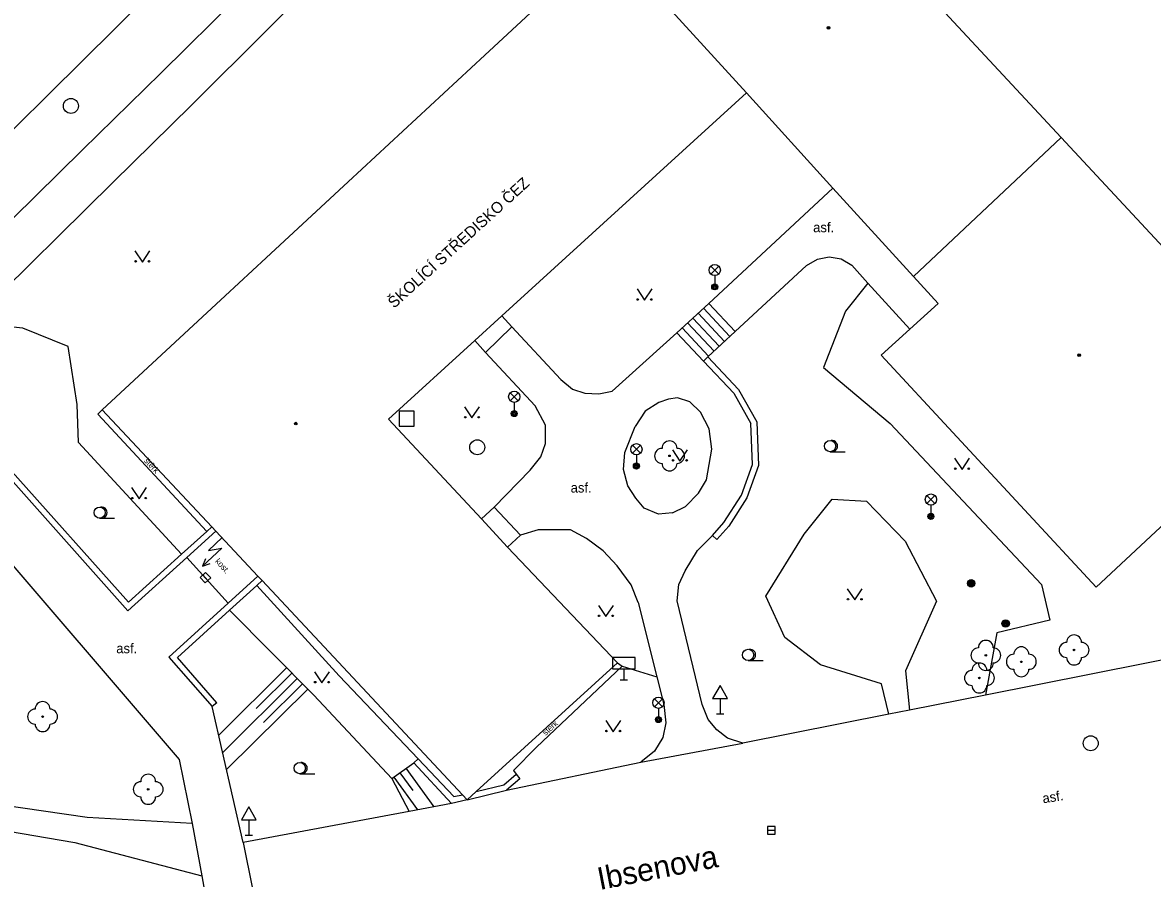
# Model space of a CAD drawing. Extents: x -598233 to -596890, y -1157848 to -1156431.
# Drawn here: x -597043.4 to -596967.9, y -1157042.3 to -1156985.2 of the extents above; entities that cross this region are included whole.
import ezdxf

# ---------------------------------------------------------------- set-up
doc = ezdxf.new("R2010")
doc.units = 0
for name, color, linetype in [('Level 10', 7, 'Continuous'), ('Level 11', 7, 'Continuous'), ('Level 14', 7, 'Continuous'), ('Level 15', 7, 'Continuous'), ('Level 21', 7, 'Continuous'), ('Level 22', 7, 'Continuous'), ('Level 23', 7, 'Continuous'), ('Level 25', 7, 'Continuous'), ('Level 26', 7, 'Continuous'), ('Level 27', 7, 'Continuous'), ('Level 33', 7, 'Continuous'), ('Level 34', 7, 'Continuous'), ('Level 36', 7, 'Continuous'), ('Level 39', 7, 'Continuous'), ('Level 40', 7, 'Continuous'), ('Level 41', 7, 'Continuous'), ('Level 49', 7, 'Continuous'), ('Level 5', 7, 'Continuous'), ('Level 7', 7, 'Continuous')]:
    doc.layers.add(name, color=color, linetype=linetype)

msp = doc.modelspace()

# ---------------------------------------------------------------- linework, layer by layer
at = {"layer": 'Level 10'}
for points in [[(-597093.49, -1157040.95), (-597092.66, -1157040.13), (-597070.05, -1157017.68), (-597057.21, -1157005.4), (-597028.29, -1156976.75), (-597022.59, -1156970.93), (-597012.03, -1156959.64)], [(-596954.24, -1157025.17), (-596979.09, -1157030.11), (-596984.17, -1157031.12), (-596985.55, -1157031.39), (-596995.29, -1157033.32)], [(-597002.11, -1157034.6), (-596995.29, -1157033.32)], [(-597011.08, -1157036.4699), (-597002.11, -1157034.6)], [(-597014.74, -1157037.35), (-597017.58, -1157037.88), (-597028.65, -1157039.95)], [(-597028.65, -1157039.95), (-597027.43, -1157046.02), (-597030.62, -1157046.71)]]:
    msp.add_lwpolyline(points, dxfattribs=at)
at = {"layer": 'Level 11'}
for points in [[(-597023.83, -1156978.25), (-597028.97, -1156983.44), (-597034.16, -1156988.6), (-597039.38, -1156993.71)], [(-597021.83, -1156980.42), (-597026.96, -1156985.61), (-597032.13, -1156990.76), (-597037.33, -1156995.87)], [(-597039.38, -1156993.71), (-597053.39, -1157007.48)], [(-597046.85, -1157005.25), (-597046.5, -1157004.91), (-597037.33, -1156995.87)], [(-596997.56, -1157003.96), (-596989.28, -1156996.26)], [(-596991.04, -1157001.43), (-596990.32, -1157001), (-596989.53, -1157000.86), (-596988.73, -1157000.98), (-596988.02, -1157001.4099)], [(-596991.04, -1157001.43), (-596995.81, -1157005.83)], [(-596988.02, -1157001.4099), (-596986.94, -1157002.6), (-596984.15, -1157005.68)], [(-596999.7, -1157005.93), (-596997.56, -1157003.96)], [(-596997.56, -1157003.96), (-596995.81, -1157005.83)], [(-597011.39, -1157004.79), (-597010.7199, -1157005.52)], [(-596998.27, -1157004.61), (-596996.51, -1157006.5)], [(-596997.92, -1157004.28), (-596996.1599, -1157006.17)], [(-597039.74, -1157010.72), (-597040.34, -1157006.85), (-597043.38, -1157005.62), (-597046.85, -1157005.25)], [(-597012.48, -1157007.24), (-597010.7199, -1157005.52)], [(-597010.7199, -1157005.52), (-597007.45, -1157009.04)], [(-596998.98, -1157005.27), (-596997.2199, -1157007.15)], [(-596998.63, -1157004.94), (-596996.87, -1157006.82)], [(-597004.01, -1157009.82), (-596999.7, -1157005.93)], [(-596999.7, -1157005.93), (-596997.93, -1157007.81)], [(-596999.34, -1157005.6), (-596997.58, -1157007.48)], [(-596995.81, -1157005.83), (-596997.64, -1157007.53)], [(-597013.2, -1157006.44), (-597012.48, -1157007.24)], [(-597009.17, -1157010.8), (-597012.48, -1157007.24)], [(-597050.8, -1157009.08), (-597048.61, -1157010.92), (-597046.34, -1157018.82), (-597032.93, -1157034.4099), (-597032.07, -1157038.68)], [(-597007.45, -1157009.04), (-597006.67, -1157009.69), (-597005.85, -1157009.95), (-597004.92, -1157010.01), (-597004.01, -1157009.82)], [(-597009.49, -1157015.1), (-597008.78, -1157014.2), (-597008.48, -1157013.32), (-597008.48, -1157012.09), (-597009.17, -1157010.8)], [(-597000, -1157017.95), (-596999.12, -1157017.53), (-596998.25, -1157016.62), (-596997.72, -1157015.75), (-596997.36, -1157013.7), (-596997.55, -1157012.34), (-596998.12, -1157011.22), (-596998.84, -1157010.53), (-596999.66, -1157010.27), (-597000.26, -1157010.36), (-597000.9099, -1157010.57), (-597001.81, -1157011.1599), (-597002.48, -1157012.18)], [(-597038.07, -1157011.07), (-597038.36, -1157011.35)], [(-597031.09, -1157019.18), (-597038.36, -1157011.35)], [(-597003.18, -1157013.92), (-597002.48, -1157012.18)], [(-597000, -1157017.95), (-597000.92, -1157018.03), (-597001.89, -1157017.63), (-597002.44, -1157016.96), (-597002.98, -1157016.15), (-597003.27, -1157015.05), (-597003.18, -1157013.92)], [(-597044.25, -1157015.01), (-597036.32, -1157023.91)], [(-597011.9, -1157017.56), (-597009.49, -1157015.1)], [(-597011.9, -1157017.56), (-597012.75, -1157018.35)], [(-597011.9, -1157017.56), (-597010.14, -1157019.44)], [(-597032.77, -1157020.7), (-597031.09, -1157019.18), (-597030.76, -1157018.88)], [(-597002.28, -1157023.94), (-597002.76, -1157022.75), (-597003.68, -1157021.49), (-597004.62, -1157020.47), (-597005.73, -1157019.65), (-597006.81, -1157019.09), (-597008.95, -1157019.07), (-597010.14, -1157019.44)], [(-597010.14, -1157019.44), (-597011, -1157020.24)], [(-596999.67, -1157023.83), (-596999.57, -1157022.73), (-596999.14, -1157021.82), (-596998.32, -1157020.45), (-596997.33, -1157019.46)], [(-597036.32, -1157023.91), (-597032.77, -1157020.7)], [(-597029.66, -1157023.98), (-597032.42, -1157020.93)], [(-597030.42, -1157030.62), (-597033.05, -1157027.6), (-597029.58, -1157024.45), (-597027.75, -1157022.79), (-597027.4, -1157022.47)], [(-597016.98, -1157034.36), (-597022.25, -1157028.82), (-597027.75, -1157022.79)], [(-597002.28, -1157023.94), (-597001.03, -1157028.89), (-597000.57, -1157030.73)], [(-596998.02, -1157030.75), (-596999.67, -1157023.83)], [(-597003.66, -1157027.96), (-597003.35, -1157028.19), (-597009.07, -1157033.58), (-597010.61, -1157035.15), (-597010.44, -1157035.4)], [(-597032.07, -1157038.68), (-597039.07, -1157038.29), (-597049.37, -1157036.79), (-597050.83, -1157036.44), (-597056.04, -1157035.05), (-597064.62, -1157032.14), (-597067.53, -1157031.15), (-597071.87, -1157029.68)], [(-597028.65, -1157039.95), (-597030.72, -1157030.88)], [(-597000.57, -1157030.73), (-597000.43, -1157031.9699), (-597000.64, -1157032.94), (-597001.19, -1157033.85), (-597002.11, -1157034.6)], [(-596995.29, -1157033.32), (-596996.33, -1157032.98), (-596997.03, -1157032.44), (-596997.62, -1157031.74), (-596998.02, -1157030.75)], [(-597074.68, -1157032.39), (-597072.64, -1157032.29), (-597067.89, -1157032.73), (-597065.43, -1157033.55), (-597056.76, -1157036.46), (-597049.69, -1157038.28), (-597039.89, -1157039.95), (-597031.4099, -1157042.18)], [(-597016.98, -1157034.36), (-597014.59, -1157036.89), (-597014.01, -1157036.76)], [(-597032.07, -1157038.68), (-597031.4099, -1157042.18)], [(-597031.4099, -1157042.18), (-597030.62, -1157046.71)]]:
    msp.add_lwpolyline(points, dxfattribs=at)
at = {"layer": 'Level 14'}
msp.add_lwpolyline([(-597018.73, -1157035.69), (-597017.27, -1157034.63)], dxfattribs=at)
at = {"layer": 'Level 15'}
for points in [[(-597025.76, -1157028.3), (-597030.28, -1157032.79)], [(-597025.41, -1157028.65), (-597027.78, -1157031.01)], [(-597025.05, -1157029.01), (-597030.02, -1157033.94)], [(-597024.7, -1157029.36), (-597027.3, -1157031.94)], [(-597024.35, -1157029.72), (-597029.76, -1157035.09)], [(-597018.6, -1157035.59), (-597017.01, -1157037.77)], [(-597018.19, -1157035.3), (-597017.33, -1157036.49)], [(-597017.79, -1157035), (-597015.92, -1157037.57)]]:
    msp.add_lwpolyline(points, dxfattribs=at)
at = {"layer": 'Level 21'}
for points in [[(-596986.94, -1157002.6), (-596988.44, -1157004.48), (-596989.9, -1157008.24), (-596985.46, -1157011.99), (-596975.36, -1157022.73), (-596974.8, -1157025.1), (-596978.34, -1157025.96), (-596979.09, -1157030.11)], [(-597032.77, -1157020.7), (-597039.65, -1157013.25), (-597039.74, -1157010.72)], [(-596985.55, -1157031.39), (-596986.03, -1157029.35), (-596990.12, -1157028.1), (-596992.5, -1157026.27), (-596993.76, -1157023.5), (-596991.2, -1157019.37), (-596989.34, -1157017.04), (-596987.04, -1157017.17), (-596984.46, -1157019.83), (-596982.37, -1157023.85), (-596984.43, -1157028.5), (-596984.17, -1157031.12)], [(-597029.58, -1157024.45), (-597023.95, -1157030.12), (-597018.73, -1157035.69), (-597017.58, -1157037.88)]]:
    msp.add_lwpolyline(points, dxfattribs=at)
at = {"layer": 'Level 22'}
for centre in [(-597000.19, -1157014.14), (-596979.07, -1157027.46), (-596973.18, -1157027.1), (-596976.7, -1157027.89), (-596979.5, -1157028.97), (-597042.05, -1157031.55), (-597035, -1157036.4)]:
    msp.add_circle(centre, 0.05, dxfattribs=at)
for centre, start, end in [((-597000.69, -1157014.14), 90, 270), ((-597000.19, -1157013.64), 0, 180), ((-596999.69, -1157014.14), 270, 90), ((-597000.19, -1157014.64), 180, 0), ((-596979.07, -1157026.96), 0, 180), ((-596973.68, -1157027.1), 90, 270), ((-596973.18, -1157026.6), 0, 180), ((-596972.68, -1157027.1), 270, 90), ((-596979.57, -1157027.46), 90, 270), ((-596978.57, -1157027.46), 270, 90), ((-596977.2, -1157027.89), 90, 270), ((-596976.7, -1157027.39), 0, 180), ((-596976.2, -1157027.89), 270, 90), ((-596979.5, -1157028.47), 0, 180), ((-596979.07, -1157027.96), 180, 0), ((-596973.18, -1157027.6), 180, 0), ((-596980, -1157028.97), 90, 270), ((-596979, -1157028.97), 270, 90), ((-596976.7, -1157028.39), 180, 0), ((-596979.5, -1157029.47), 180, 0), ((-597042.55, -1157031.55), 90, 270), ((-597042.05, -1157031.05), 0, 180), ((-597041.55, -1157031.55), 270, 90), ((-597042.05, -1157032.05), 180, 0), ((-597035, -1157035.9), 0, 180), ((-597035.5, -1157036.4), 90, 270), ((-597034.5, -1157036.4), 270, 90), ((-597035, -1157036.9), 180, 0)]:
    msp.add_arc(centre, 0.5, start, end, dxfattribs=at)
at = {"layer": 'Level 23'}
msp.add_lwpolyline([(-597003.35, -1157028.19), (-597001.03, -1157028.89)], dxfattribs=at)
at = {"layer": 'Level 25'}
for centre, radius in [((-596980.05, -1157022.65), 0.25), ((-596980.05, -1157022.65), 0.2), ((-596980.05, -1157022.65), 0.15), ((-596980.05, -1157022.65), 0.1), ((-596980.05, -1157022.65), 0.05), ((-596977.75, -1157025.33), 0.25), ((-596977.75, -1157025.33), 0.2), ((-596977.75, -1157025.33), 0.15), ((-596977.75, -1157025.33), 0.1), ((-596977.75, -1157025.33), 0.05)]:
    msp.add_circle(centre, radius, dxfattribs=at)
at = {"layer": 'Level 26'}
msp.add_lwpolyline([(-597018.24, -1157012.15), (-597017.24, -1157012.15), (-597017.24, -1157011.15), (-597018.24, -1157011.15)], close=True, dxfattribs=at)
at = {"layer": 'Level 27'}
for p, q in [((-597031.0123, -1157022.4554), (-597031.3477, -1157022.0846)), ((-596993.64, -1157039.14), (-596993.14, -1157039.14))]:
    msp.add_line(p, q, dxfattribs=at)
for points in [[(-597030.8269, -1157022.2876), (-597031.1624, -1157021.9169), (-597031.5331, -1157022.2524), (-597031.1976, -1157022.6231)], [(-596993.64, -1157039.39), (-596993.14, -1157039.39), (-596993.14, -1157038.89), (-596993.64, -1157038.89)]]:
    msp.add_lwpolyline(points, close=True, dxfattribs=at)
for centre in [(-597040.1599, -1156990.78), (-597013.03, -1157013.57), (-596972.07, -1157033.33)]:
    msp.add_circle(centre, 0.5, dxfattribs=at)
at = {"layer": 'Level 33'}
for p, q in [((-596997.435, -1157002), (-596996.905, -1157001.47)), ((-596997.435, -1157001.47), (-596996.905, -1157002)), ((-596997.17, -1157002.11), (-596997.17, -1157002.86)), ((-597010.825, -1157010.46), (-597010.295, -1157009.93)), ((-597010.825, -1157009.93), (-597010.295, -1157010.46)), ((-597010.56, -1157010.57), (-597010.56, -1157011.32)), ((-597002.665, -1157013.96), (-597002.135, -1157013.43)), ((-597002.665, -1157013.43), (-597002.135, -1157013.96)), ((-597002.4, -1157014.07), (-597002.4, -1157014.82)), ((-596983.005, -1157017.32), (-596982.475, -1157016.79)), ((-596983.005, -1157016.79), (-596982.475, -1157017.32)), ((-596982.74, -1157017.43), (-596982.74, -1157018.18)), ((-597001.195, -1157030.89), (-597000.665, -1157030.36)), ((-597001.195, -1157030.36), (-597000.665, -1157030.89)), ((-597000.93, -1157031), (-597000.93, -1157031.75))]:
    msp.add_line(p, q, dxfattribs=at)
for centre, radius in [((-596997.17, -1157001.735), 0.375), ((-596997.17, -1157002.86), 0.2), ((-596997.17, -1157002.86), 0.1445), ((-596997.17, -1157002.86), 0.0876), ((-597010.56, -1157010.195), 0.375), ((-597010.56, -1157011.32), 0.2), ((-597010.56, -1157011.32), 0.1445), ((-597010.56, -1157011.32), 0.0876), ((-597002.4, -1157013.695), 0.375), ((-597002.4, -1157014.82), 0.2), ((-597002.4, -1157014.82), 0.1445), ((-597002.4, -1157014.82), 0.0876), ((-596982.74, -1157017.055), 0.375), ((-596982.74, -1157018.18), 0.2), ((-596982.74, -1157018.18), 0.1445), ((-596982.74, -1157018.18), 0.0876), ((-597000.93, -1157030.625), 0.375), ((-597000.93, -1157031.75), 0.2), ((-597000.93, -1157031.75), 0.1445), ((-597000.93, -1157031.75), 0.0876)]:
    msp.add_circle(centre, radius, dxfattribs=at)
at = {"layer": 'Level 34'}
for p, q in [((-597003.24, -1157028.35), (-597003.24, -1157029.1)), ((-597003.49, -1157029.1), (-597002.99, -1157029.1)), ((-596996.81, -1157030.342), (-596996.81, -1157031.36)), ((-596997.06, -1157031.36), (-596996.56, -1157031.36)), ((-597028.28, -1157038.442), (-597028.28, -1157039.46)), ((-597028.53, -1157039.46), (-597028.03, -1157039.46))]:
    msp.add_line(p, q, dxfattribs=at)
for points in [[(-597003.99, -1157028.35), (-597002.49, -1157028.35), (-597002.49, -1157027.6), (-597003.99, -1157027.6)], [(-596997.31, -1157030.342), (-596996.31, -1157030.342), (-596996.81, -1157029.476)], [(-597028.78, -1157038.442), (-597027.78, -1157038.442), (-597028.28, -1157037.576)]]:
    msp.add_lwpolyline(points, close=True, dxfattribs=at)
at = {"layer": 'Level 36'}
for p, q in [((-596989.47, -1157013.865), (-596988.47, -1157013.865)), ((-597038.24, -1157018.305), (-597037.24, -1157018.305)), ((-596994.94, -1157027.805), (-596993.94, -1157027.805)), ((-597024.88, -1157035.365), (-597023.88, -1157035.365))]:
    msp.add_line(p, q, dxfattribs=at)
for points in [[(-597035.89, -1157000.45), (-597035.39, -1157001.2), (-597034.89, -1157000.45)], [(-597002.36, -1157003), (-597001.86, -1157003.75), (-597001.36, -1157003)], [(-597013.88, -1157010.86), (-597013.38, -1157011.61), (-597012.88, -1157010.86)], [(-597000, -1157013.74), (-596999.5, -1157014.49), (-596999, -1157013.74)], [(-596981.16, -1157014.3), (-596980.66, -1157015.05), (-596980.16, -1157014.3)], [(-597036.11, -1157016.26), (-597035.61, -1157017.01), (-597035.11, -1157016.26)], [(-597030.07, -1157019.6), (-597030.9823, -1157020.4546), (-597030.0931, -1157020.3067), (-597031.3702, -1157021.5031)], [(-597031.1631, -1157021.009), (-597031.3702, -1157021.5031), (-597030.8636, -1157021.3286)], [(-596988.32, -1157023.01), (-596987.82, -1157023.76), (-596987.32, -1157023.01)], [(-597004.94, -1157024.12), (-597004.44, -1157024.87), (-597003.94, -1157024.12)], [(-597023.9, -1157028.55), (-597023.4, -1157029.3), (-597022.9, -1157028.55)], [(-597004.45, -1157031.81), (-597003.95, -1157032.56), (-597003.45, -1157031.81)]]:
    msp.add_lwpolyline(points, dxfattribs=at)
for centre, radius in [((-597035.8402, -1157001.1498), 0.05), ((-597034.9408, -1157001.1498), 0.05), ((-597002.3102, -1157003.6998), 0.05), ((-597001.4108, -1157003.6998), 0.05), ((-597013.8302, -1157011.5598), 0.05), ((-597012.9308, -1157011.5598), 0.05), ((-596989.47, -1157013.4896), 0.375), ((-596999.9502, -1157014.4398), 0.05), ((-596999.0508, -1157014.4398), 0.05), ((-596981.1102, -1157014.9998), 0.05), ((-596980.2108, -1157014.9998), 0.05), ((-597038.24, -1157017.9296), 0.375), ((-597036.0602, -1157016.9598), 0.05), ((-597035.1608, -1157016.9598), 0.05), ((-596988.2702, -1157023.7098), 0.05), ((-596987.3708, -1157023.7098), 0.05), ((-597004.8902, -1157024.8198), 0.05), ((-597003.9908, -1157024.8198), 0.05), ((-596994.94, -1157027.4296), 0.375), ((-597023.8502, -1157029.2498), 0.05), ((-597022.9508, -1157029.2498), 0.05), ((-597004.4002, -1157032.5098), 0.05), ((-597003.5008, -1157032.5098), 0.05), ((-597024.88, -1157034.9896), 0.375)]:
    msp.add_circle(centre, radius, dxfattribs=at)
for centre in [(-596989.345, -1157013.4896), (-597038.115, -1157017.9296), (-596994.815, -1157027.4296), (-597024.755, -1157034.9896)]:
    msp.add_arc(centre, 0.375, 260.405931, 99.594069, dxfattribs=at)
at = {"layer": 'Level 39'}
for centre, radius in [((-596989.57, -1156985.56), 0.09), ((-596989.57, -1156985.56), 0.0398), ((-596972.84, -1157007.42), 0.09), ((-596972.84, -1157007.42), 0.0398), ((-597025.15, -1157011.99), 0.09), ((-597025.15, -1157011.99), 0.0398)]:
    msp.add_circle(centre, radius, dxfattribs=at)
at = {"layer": 'Level 5'}
for points in [[(-596995.56, -1156969.74), (-596974.03, -1156992.89)], [(-597004.31, -1156979.76), (-597038.07, -1157011.07)], [(-597004.31, -1156979.76), (-596995.06, -1156989.9099)], [(-596995.06, -1156989.9099), (-597011.39, -1157004.79)], [(-596995.06, -1156989.9099), (-596989.28, -1156996.26)], [(-596974.03, -1156992.89), (-596983.9, -1157002.17)], [(-596974.03, -1156992.89), (-596958, -1157010.14)], [(-596989.28, -1156996.26), (-596983.9, -1157002.17)], [(-596983.9, -1157002.17), (-596982.26, -1157003.96)], [(-596982.26, -1157003.96), (-596984.15, -1157005.68)], [(-597011.39, -1157004.79), (-597013.2, -1157006.44)], [(-596984.15, -1157005.68), (-596986.05, -1157007.4099)], [(-597013.2, -1157006.44), (-597018.95, -1157011.68)], [(-596986.05, -1157007.4099), (-596971.71, -1157022.9)], [(-597030.76, -1157018.88), (-597038.07, -1157011.07)], [(-597018.95, -1157011.68), (-597012.75, -1157018.35)], [(-596965.75, -1157017.36), (-596971.71, -1157022.9)], [(-597012.75, -1157018.35), (-597011, -1157020.24)], [(-597030.76, -1157018.88), (-597030.48, -1157019.17), (-597027.67, -1157022.17)], [(-597011, -1157020.24), (-597003.66, -1157027.96)], [(-597027.4, -1157022.47), (-597027.67, -1157022.17)], [(-597027.4, -1157022.47), (-597014.01, -1157036.76)], [(-597003.66, -1157027.96), (-597013.1, -1157036.55)], [(-597014.01, -1157036.76), (-597013.7, -1157037.1)], [(-597013.1, -1157036.55), (-597013.7, -1157037.1)]]:
    msp.add_lwpolyline(points, dxfattribs=at)
at = {"layer": 'Level 7'}
for points in [[(-596997.64, -1157007.53), (-596997.93, -1157007.81)], [(-596997.93, -1157007.81), (-596995.9, -1157009.95), (-596994.76, -1157011.98)], [(-596997.64, -1157007.53), (-596995.58, -1157009.71), (-596994.37, -1157011.87), (-596994.24, -1157014.78), (-596995.02, -1157016.94), (-596996.24, -1157018.84), (-596997.04, -1157019.7199), (-596997.33, -1157019.46)], [(-596997.33, -1157019.46), (-596996.56, -1157018.6), (-596995.38, -1157016.76), (-596994.64, -1157014.7199), (-596994.76, -1157011.98)], [(-597036.35, -1157024.48), (-597044.55, -1157015.28)], [(-597030.48, -1157019.17), (-597032.42, -1157020.93)], [(-597032.42, -1157020.93), (-597036.35, -1157024.48)], [(-597027.67, -1157022.17), (-597029.66, -1157023.98), (-597033.61, -1157027.57), (-597030.72, -1157030.88)], [(-597030.42, -1157030.62), (-597030.72, -1157030.88)], [(-597014.74, -1157037.35), (-597017.27, -1157034.63), (-597016.98, -1157034.36)], [(-597013.1, -1157036.55), (-597011.26, -1157036.1), (-597010.44, -1157035.4), (-597010.18, -1157035.7), (-597011.08, -1157036.4699)], [(-597013.7, -1157037.1), (-597011.08, -1157036.4699)], [(-597013.7, -1157037.1), (-597014.74, -1157037.35)]]:
    msp.add_lwpolyline(points, dxfattribs=at)

# ---------------------------------------------------------------- texts
at = {"layer": 'Level 40'}
for p in [(-596990.6, -1156999.21), (-597006.79, -1157016.59), (-597037.13, -1157027.32)]:
    msp.add_text('asf.', height=0.65, dxfattribs=at).set_placement(p)
for s, height, rotation, p in [('štěrk', 0.4, 312.868208, (-597035.3, -1157014.5)), ('kost.', 0.4, 312.142513, (-597030.56, -1157021.2)), ('štěrk', 0.4, 42.300866, (-597008.46, -1157032.84)), ('asf.', 0.65, 9, (-596975.24, -1157037.34))]:
    msp.add_text(s, height=height, rotation=rotation, dxfattribs=at).set_placement(p)
at = {"layer": 'Level 41'}
msp.add_text('ŠKOLÍCÍ STŘEDISKO ČEZ', height=0.75, rotation=42.35237, dxfattribs=at).set_placement((-597018.58, -1157004.33))
at = {"layer": 'Level 49'}
msp.add_text('Ibsenova', height=1.5, rotation=11, dxfattribs=at).set_placement((-597004.85, -1157043.13))

doc.saveas('drawing.dxf')
